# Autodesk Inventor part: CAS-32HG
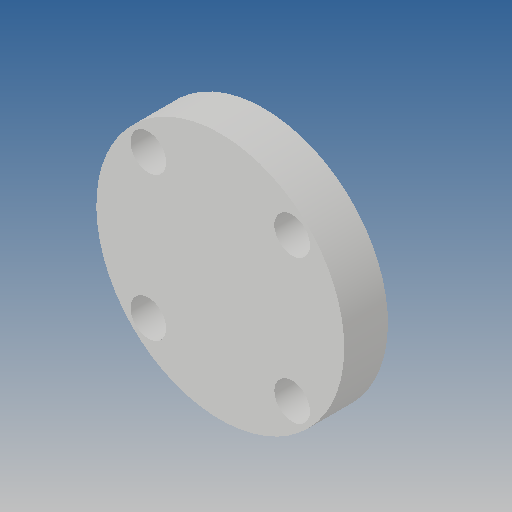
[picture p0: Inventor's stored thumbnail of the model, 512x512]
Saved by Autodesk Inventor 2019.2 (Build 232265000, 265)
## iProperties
Created: 2010-02
Part Number: CAS-32HG
Material: Ogólny
Document SubType Name: Modeling
Designer: CADENGINEERING4
Density: 1 g/cm^3
Appearance: Domyślna
Author: CADENGINEERING4
Revision Number: 1LAST_VERSION
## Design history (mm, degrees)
feature "Baza1"
node "Bryła1"
